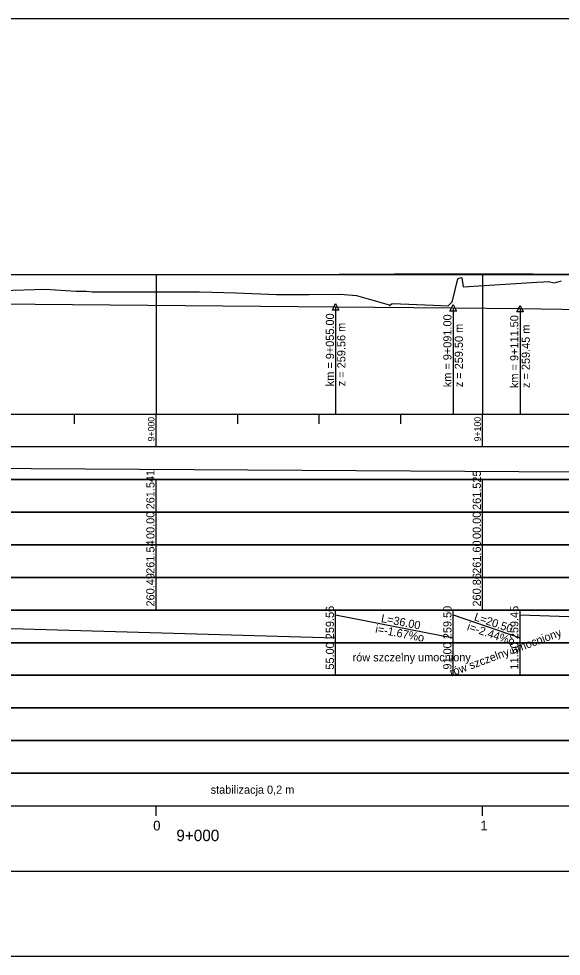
# Model space of a CAD drawing. Extents: x 6445630 to 6518227, y 5499240 to 5511716.
# Drawn here: x 6453589.1 to 6453755.4, y 5506751.3 to 5507038.3 of the extents above; entities that cross this region are included whole.
import ezdxf

# ---------------------------------------------------------------- set-up
doc = ezdxf.new("R2010")
doc.units = 0
for name, color, linetype in [('TOR_PROF-opisy pomocnicze', 7, 'Continuous'), ('TOR_PROF-rowy otwarte', 7, 'Continuous'), ('TOR_PROF-tabelka-geometria T1', 7, 'Continuous'), ('TOR_PROF-tabelka-kilometracja', 7, 'Continuous'), ('TOR_PROF-tabelka-odleglosci T1', 7, 'Continuous'), ('TOR_PROF-tabelka-pochylenia proj T1', 7, 'Continuous'), ('TOR_PROF-tabelka-rodzaj rowu T1', 7, 'Continuous'), ('TOR_PROF-tabelka-rowyT1', 7, 'Continuous'), ('TOR_PROF-tabelka-rurociagi T1', 7, 'Continuous'), ('TOR_PROF-tabelka-rzedne istn T1', 7, 'Continuous'), ('TOR_PROF-tabelka-rzedne proj T1', 7, 'Continuous'), ('TOR_PROF-tabelka-teren istniejacy T1', 7, 'Continuous'), ('TOR_PROF-tabelka-warstwa ochronna T1', 7, 'Continuous'), ('TOR_PROF-tor istniejacy T2', 7, 'Continuous'), ('TOR_PROF-tor projektowany', 7, 'Continuous'), ('TOR_PROF-uklad odniesienia', 7, 'Continuous'), ('TOR_PROF-warstwa ochronna', 7, 'Continuous'), ('TOR_RAMKI-dodatkowe3', 7, 'Continuous'), ('TOR_RAMKI-MASKA WYCIECIA', 7, 'Continuous')]:
    doc.layers.add(name, color=color, linetype=linetype)

msp = doc.modelspace()

# ---------------------------------------------------------------- linework, layer by layer
at = {"layer": 'TOR_PROF-opisy pomocnicze'}
for p, q in [((6453686.21, 5506950.1), (6453686.21, 5506924.9)), ((6453722.21, 5506949.8), (6453722.21, 5506924.6)), ((6453742.71, 5506949.55), (6453742.71, 5506924.35))]:
    msp.add_line(p, q, dxfattribs=at)
for points in [[(6453686.21, 5506951.1), (6453687.21, 5506949.1), (6453685.21, 5506949.1)], [(6453722.21, 5506950.8), (6453723.21, 5506948.8), (6453721.21, 5506948.8)], [(6453742.71, 5506950.55), (6453743.71, 5506948.55), (6453741.71, 5506948.55)]]:
    msp.add_lwpolyline(points, close=True, dxfattribs=at)
at = {"layer": 'TOR_PROF-rowy otwarte'}
for p, q in [((6453441.21, 5506952.3), (6453686.21, 5506950.1)), ((6453686.21, 5506950.1), (6453722.21, 5506949.8)), ((6453722.21, 5506949.8), (6453742.71, 5506949.55)), ((6453742.71, 5506949.55), (6453949.21, 5506947.3))]:
    msp.add_line(p, q, dxfattribs=at)
for points in [[(6453686.21, 5506950.1), (6453686.21, 5506922.3), (6453686.21, 5506917.3), (6453686.21, 5506917.3)], [(6453722.21, 5506949.8), (6453722.21, 5506922.3), (6453722.21, 5506917.3), (6453722.21, 5506917.3)], [(6453742.71, 5506949.55), (6453742.71, 5506922.3), (6453742.71, 5506917.3), (6453742.71, 5506917.3)]]:
    msp.add_lwpolyline(points, dxfattribs=at)
at = {"layer": 'TOR_PROF-tabelka-geometria T1'}
for points in [[(6452423.2, 5506777.3), (6452515.66, 5506777.3), (6452515.66, 5506777.3), (6452555.66, 5506779.97), (6452555.66, 5506779.97), (6452695.25, 5506779.97), (6452695.25, 5506779.97), (6452735.25, 5506777.3), (6452735.25, 5506777.3), (6458247.17, 5506777.3)], [(6452331.21, 5506777.3), (6459531.21, 5506777.3)]]:
    msp.add_lwpolyline(points, dxfattribs=at)
at = {"layer": 'TOR_PROF-tabelka-kilometracja'}
for points in [[(6453631.21, 5506794.3), (6453631.21, 5506797.3)], [(6453631.21, 5506794.3), (6453631.21, 5506797.3)], [(6453731.21, 5506794.3), (6453731.21, 5506797.3)]]:
    msp.add_lwpolyline(points, dxfattribs=at)
at = {"layer": 'TOR_PROF-tabelka-odleglosci T1'}
msp.add_lwpolyline([(6452331.21, 5506877.3), (6459531.21, 5506877.3), (6459531.21, 5506887.3), (6452331.21, 5506887.3)], close=True, dxfattribs=at)
for points in [[(6453631.21, 5506877.3), (6453631.21, 5506887.3)], [(6453731.21, 5506877.3), (6453731.21, 5506887.3)]]:
    msp.add_lwpolyline(points, dxfattribs=at)
at = {"layer": 'TOR_PROF-tabelka-pochylenia proj T1'}
msp.add_lwpolyline([(6452331.21, 5506897.3), (6459531.21, 5506897.3), (6459531.21, 5506907.3), (6452331.21, 5506907.3)], close=True, dxfattribs=at)
msp.add_lwpolyline([(6452746.21, 5506905.8), (6453891.74, 5506898.8)], dxfattribs=at)
at = {"layer": 'TOR_PROF-tabelka-rodzaj rowu T1'}
for points in [[(6452331.21, 5506837.3), (6459531.21, 5506837.3), (6459531.21, 5506847.3), (6452331.21, 5506847.3)], [(6452331.21, 5506817.3), (6459531.21, 5506817.3), (6459531.21, 5506827.3), (6452331.21, 5506827.3)]]:
    msp.add_lwpolyline(points, close=True, dxfattribs=at)
for points in [[(6453686.21, 5506837.3), (6453686.21, 5506847.3)], [(6453722.21, 5506837.3), (6453722.21, 5506847.3)], [(6453742.71, 5506837.3), (6453742.71, 5506847.3)]]:
    msp.add_lwpolyline(points, dxfattribs=at)
at = {"layer": 'TOR_PROF-tabelka-rowyT1'}
msp.add_lwpolyline([(6452331.21, 5506847.3), (6459531.21, 5506847.3), (6459531.21, 5506857.3), (6452331.21, 5506857.3)], close=True, dxfattribs=at)
for points in [[(6453441.21, 5506855.8), (6453686.21, 5506848.8)], [(6453686.21, 5506847.3), (6453686.21, 5506857.3)], [(6453686.21, 5506855.8), (6453722.21, 5506848.8)], [(6453722.21, 5506847.3), (6453722.21, 5506857.3)], [(6453722.21, 5506855.8), (6453742.71, 5506848.8)], [(6453742.71, 5506847.3), (6453742.71, 5506857.3)], [(6453742.71, 5506855.8), (6453949.21, 5506848.8)]]:
    msp.add_lwpolyline(points, dxfattribs=at)
at = {"layer": 'TOR_PROF-tabelka-rurociagi T1'}
msp.add_lwpolyline([(6452331.21, 5506827.3), (6459531.21, 5506827.3), (6459531.21, 5506837.3), (6452331.21, 5506837.3)], close=True, dxfattribs=at)
at = {"layer": 'TOR_PROF-tabelka-rzedne istn T1'}
msp.add_lwpolyline([(6452331.21, 5506867.3), (6459531.21, 5506867.3), (6459531.21, 5506877.3), (6452331.21, 5506877.3)], close=True, dxfattribs=at)
for points in [[(6453631.21, 5506867.3), (6453631.21, 5506877.3)], [(6453731.21, 5506867.3), (6453731.21, 5506877.3)], [(6453631.21, 5506857.3), (6453631.21, 5506867.3)], [(6453631.21, 5506857.3), (6453631.21, 5506867.3)], [(6453631.21, 5506857.3), (6453631.21, 5506867.3)], [(6453731.21, 5506857.3), (6453731.21, 5506867.3)], [(6453731.21, 5506857.3), (6453731.21, 5506867.3)], [(6453731.21, 5506857.3), (6453731.21, 5506867.3)]]:
    msp.add_lwpolyline(points, dxfattribs=at)
at = {"layer": 'TOR_PROF-tabelka-rzedne proj T1'}
msp.add_lwpolyline([(6452331.21, 5506887.3), (6459531.21, 5506887.3), (6459531.21, 5506897.3), (6452331.21, 5506897.3)], close=True, dxfattribs=at)
for points in [[(6453631.21, 5506887.3), (6453631.21, 5506897.3)], [(6453731.21, 5506887.3), (6453731.21, 5506897.3)]]:
    msp.add_lwpolyline(points, dxfattribs=at)
at = {"layer": 'TOR_PROF-tabelka-teren istniejacy T1'}
msp.add_lwpolyline([(6452331.21, 5506857.3), (6459531.21, 5506857.3), (6459531.21, 5506867.3), (6452331.21, 5506867.3)], close=True, dxfattribs=at)
msp.add_lwpolyline([(6452331.21, 5506857.3), (6459531.21, 5506857.3), (6459531.21, 5506867.3), (6452331.21, 5506867.3)], close=True, dxfattribs=at)
msp.add_lwpolyline([(6452331.21, 5506857.3), (6459531.21, 5506857.3), (6459531.21, 5506867.3), (6452331.21, 5506867.3)], close=True, dxfattribs=at)
at = {"layer": 'TOR_PROF-tabelka-warstwa ochronna T1'}
msp.add_lwpolyline([(6452331.21, 5506807.3), (6459531.21, 5506807.3), (6459531.21, 5506817.3), (6452331.21, 5506817.3)], close=True, dxfattribs=at)
at = {"layer": 'TOR_PROF-tor istniejacy T2'}
msp.add_lwpolyline([(6453023.63, 5506960.15), (6453075.64, 5506960.15), (6453123.58, 5506960.15), (6453172.17, 5506960.05), (6453222.54, 5506960.05), (6453273.53, 5506959.85), (6453323.54, 5506959.95), (6453373.26, 5506960.1), (6453422.16, 5506959.9), (6453472.58, 5506960), (6453521.34, 5506959.95), (6453572.04, 5506960), (6453620.5, 5506960), (6453670.33, 5506960.05), (6453721.23, 5506960.35), (6453772.37, 5506960.15)], dxfattribs=at)
at = {"layer": 'TOR_PROF-tor projektowany'}
for p, q in [((6452746.21, 5506960.7), (6453891.74, 5506959.8)), ((6452746.21, 5506960.7), (6453891.74, 5506959.8)), ((6453723.64, 5506958.64), (6453724.63, 5506959.08)), ((6453724.63, 5506959.08), (6453724.86, 5506958.97)), ((6453724.86, 5506958.97), (6453725.26, 5506956.25)), ((6453721.99, 5506951.95), (6453723.64, 5506958.64)), ((6453725.26, 5506956.25), (6453747.91, 5506957.67)), ((6453747.91, 5506957.67), (6453749.99, 5506957.77)), ((6453749.99, 5506957.77), (6453751.3, 5506957.91)), ((6453751.3, 5506957.91), (6453753.32, 5506957.44)), ((6453753.32, 5506957.44), (6453755.46, 5506958.04)), ((6453584.02, 5506955.08), (6453597.26, 5506955.56)), ((6453597.26, 5506955.56), (6453606.72, 5506954.95)), ((6453606.72, 5506954.95), (6453609.09, 5506954.95)), ((6453609.09, 5506954.95), (6453609.74, 5506954.86)), ((6453609.74, 5506954.86), (6453611.72, 5506954.71)), ((6453611.72, 5506954.71), (6453643.04, 5506954.75)), ((6453643.04, 5506954.75), (6453643.71, 5506954.72)), ((6453643.71, 5506954.72), (6453644.52, 5506954.7)), ((6453644.52, 5506954.7), (6453655.78, 5506954.38)), ((6453655.78, 5506954.38), (6453668.13, 5506953.89)), ((6453668.13, 5506953.89), (6453674.09, 5506953.86)), ((6453674.09, 5506953.86), (6453678.12, 5506953.92)), ((6453678.12, 5506953.92), (6453687.63, 5506953.97)), ((6453687.63, 5506953.97), (6453692.62, 5506953.6)), ((6453692.62, 5506953.6), (6453702.62, 5506950.69)), ((6453702.62, 5506950.69), (6453702.76, 5506950.38)), ((6453702.76, 5506950.38), (6453703.1, 5506950.87)), ((6453703.1, 5506950.87), (6453703.56, 5506951.14)), ((6453703.56, 5506951.14), (6453716.16, 5506950.58)), ((6453716.16, 5506950.58), (6453720.67, 5506950.39)), ((6453720.67, 5506950.39), (6453721.71, 5506951.47)), ((6453721.71, 5506951.47), (6453721.88, 5506951.59)), ((6453721.88, 5506951.59), (6453721.93, 5506951.65)), ((6453721.93, 5506951.65), (6453721.99, 5506951.95))]:
    msp.add_line(p, q, dxfattribs=at)
for points in [[(6453631.21, 5506960.01), (6453631.21, 5506922.3), (6453631.21, 5506917.3), (6453631.21, 5506917.3)], [(6453631.21, 5506960.01), (6453631.21, 5506922.3), (6453631.21, 5506917.3), (6453631.21, 5506917.3)], [(6453731.21, 5506959.93), (6453731.21, 5506922.3), (6453731.21, 5506917.3), (6453731.21, 5506917.3)], [(6453731.21, 5506959.93), (6453731.21, 5506922.3), (6453731.21, 5506917.3), (6453731.21, 5506917.3)]]:
    msp.add_lwpolyline(points, dxfattribs=at)
at = {"layer": 'TOR_PROF-uklad odniesienia'}
for p, q in [((6452331.21, 5506917.3), (6459531.21, 5506917.3)), ((6453606.21, 5506914.3), (6453606.21, 5506917.3)), ((6453631.21, 5506907.3), (6453631.21, 5506917.3)), ((6453656.21, 5506914.3), (6453656.21, 5506917.3)), ((6453681.21, 5506914.3), (6453681.21, 5506917.3)), ((6453706.21, 5506914.3), (6453706.21, 5506917.3)), ((6453731.21, 5506907.3), (6453731.21, 5506917.3))]:
    msp.add_line(p, q, dxfattribs=at)
at = {"layer": 'TOR_PROF-warstwa ochronna'}
msp.add_lwpolyline([(6452331.21, 5506797.3), (6459531.21, 5506797.3), (6459531.21, 5506807.3), (6452331.21, 5506807.3)], close=True, dxfattribs=at)
at = {"layer": 'TOR_RAMKI-dodatkowe3'}
for p, q in [((6453723.64, 5506958.64), (6453724.63, 5506959.08)), ((6453724.63, 5506959.08), (6453724.86, 5506958.97)), ((6453724.86, 5506958.97), (6453725.26, 5506956.25)), ((6453721.99, 5506951.95), (6453723.64, 5506958.64)), ((6453725.26, 5506956.25), (6453747.91, 5506957.67)), ((6453747.91, 5506957.67), (6453749.99, 5506957.77)), ((6453749.99, 5506957.77), (6453751.3, 5506957.91)), ((6453751.3, 5506957.91), (6453753.32, 5506957.44)), ((6453753.32, 5506957.44), (6453755.46, 5506958.04)), ((6453584.02, 5506955.08), (6453597.26, 5506955.56)), ((6453597.26, 5506955.56), (6453606.72, 5506954.95)), ((6453606.72, 5506954.95), (6453609.09, 5506954.95)), ((6453609.09, 5506954.95), (6453609.74, 5506954.86)), ((6453609.74, 5506954.86), (6453611.72, 5506954.71)), ((6453611.72, 5506954.71), (6453643.04, 5506954.75)), ((6453643.04, 5506954.75), (6453643.71, 5506954.72)), ((6453643.71, 5506954.72), (6453644.52, 5506954.7)), ((6453644.52, 5506954.7), (6453655.78, 5506954.38)), ((6453655.78, 5506954.38), (6453668.13, 5506953.89)), ((6453668.13, 5506953.89), (6453674.09, 5506953.86)), ((6453674.09, 5506953.86), (6453678.12, 5506953.92)), ((6453678.12, 5506953.92), (6453687.63, 5506953.97)), ((6453687.63, 5506953.97), (6453692.62, 5506953.6)), ((6453692.62, 5506953.6), (6453702.62, 5506950.69)), ((6453702.62, 5506950.69), (6453702.76, 5506950.38)), ((6453702.76, 5506950.38), (6453703.1, 5506950.87)), ((6453703.1, 5506950.87), (6453703.56, 5506951.14)), ((6453703.56, 5506951.14), (6453716.16, 5506950.58)), ((6453716.16, 5506950.58), (6453720.67, 5506950.39)), ((6453720.67, 5506950.39), (6453721.71, 5506951.47)), ((6453721.71, 5506951.47), (6453721.88, 5506951.59)), ((6453721.88, 5506951.59), (6453721.93, 5506951.65)), ((6453721.93, 5506951.65), (6453721.99, 5506951.95))]:
    msp.add_line(p, q, dxfattribs=at)
at = {"layer": 'TOR_RAMKI-MASKA WYCIECIA'}
msp.add_lwpolyline([(6452266.27, 5506751.3), (6453906.27, 5506751.3), (6453906.27, 5507038.3), (6452266.27, 5507038.3)], close=True, dxfattribs=at)

# ---------------------------------------------------------------- texts
at = {"layer": 'TOR_PROF-opisy pomocnicze'}
for s, p in [('km = 9+055.00', (6453685.71, 5506925.8)), ('km = 9+091.00', (6453721.71, 5506925.5)), ('km = 9+111.50', (6453742.21, 5506925.25)), ('z = 259.56 m', (6453689.21, 5506925.8)), ('z = 259.50 m', (6453725.21, 5506925.5)), ('z = 259.45 m', (6453745.71, 5506925.25))]:
    msp.add_text(s, height=2.5, rotation=90, dxfattribs=at).set_placement(p)
at = {"layer": 'TOR_PROF-tabelka-kilometracja'}
for s, p in [('0', (6453630.32, 5506789.8)), ('1', (6453730.56, 5506789.8))]:
    msp.add_text(s, height=3, dxfattribs=at).set_placement(p)
msp.add_text('9+000', height=3.5, rotation=360, dxfattribs=at).set_placement((6453637.42, 5506786.55))
at = {"layer": 'TOR_PROF-tabelka-odleglosci T1'}
for p in [(6453630.71, 5506879.04), (6453730.71, 5506879.04)]:
    msp.add_text('00.00', height=2.5, rotation=90, dxfattribs=at).set_placement(p)
at = {"layer": 'TOR_PROF-tabelka-rodzaj rowu T1'}
for s, p in [('55.00', (6453685.71, 5506839.05)), ('91.00', (6453721.71, 5506839.05)), ('11.50', (6453742.21, 5506839.05))]:
    msp.add_text(s, height=2.5, rotation=90, dxfattribs=at).set_placement(p)
at = {"layer": 'TOR_PROF-tabelka-rowyT1'}
for s, rotation, p in [('259.56', 90, (6453685.71, 5506848.36)), ('259.50', 90, (6453721.71, 5506848.37)), ('259.45', 90, (6453742.21, 5506848.36)), ('L=36.00', 348.9965, (6453699.99, 5506853.63)), ('L=20.50', 341.1468, (6453728.46, 5506854.2)), ('i=-1.67%o', 348.9965, (6453698.24, 5506850.41)), ('i=-2.44%o', 341.1468, (6453726.29, 5506851.24)), ('rów szczelny umocniony', 20.2607, (6453721.69, 5506836.89)), ('rów szczelny umocniony', 0.087, (6453691.42, 5506841.54))]:
    msp.add_text(s, height=2.5, rotation=rotation, dxfattribs=at).set_placement(p)
at = {"layer": 'TOR_PROF-tabelka-rzedne istn T1'}
for s, p in [('261.54', (6453630.71, 5506868.37)), ('261.60', (6453730.71, 5506868.37)), ('260.49', (6453630.71, 5506858.37)), ('260.86', (6453730.71, 5506858.36))]:
    msp.add_text(s, height=2.5, rotation=90, dxfattribs=at).set_placement(p)
at = {"layer": 'TOR_PROF-tabelka-rzedne proj T1'}
for s, p in [('261.541', (6453630.71, 5506888.11)), ('261.525', (6453730.71, 5506887.93))]:
    msp.add_text(s, height=2.5, rotation=90, dxfattribs=at).set_placement(p)
at = {"layer": 'TOR_PROF-uklad odniesienia'}
for s, p in [('9+000', (6453630.71, 5506908.91)), ('9+100', (6453730.71, 5506908.91))]:
    msp.add_text(s, height=2, rotation=90, dxfattribs=at).set_placement(p)
at = {"layer": 'TOR_PROF-warstwa ochronna'}
msp.add_text('stabilizacja 0,2 m', height=2.5, dxfattribs=at).set_placement((6453647.92, 5506801.05))

doc.saveas('drawing.dxf')
